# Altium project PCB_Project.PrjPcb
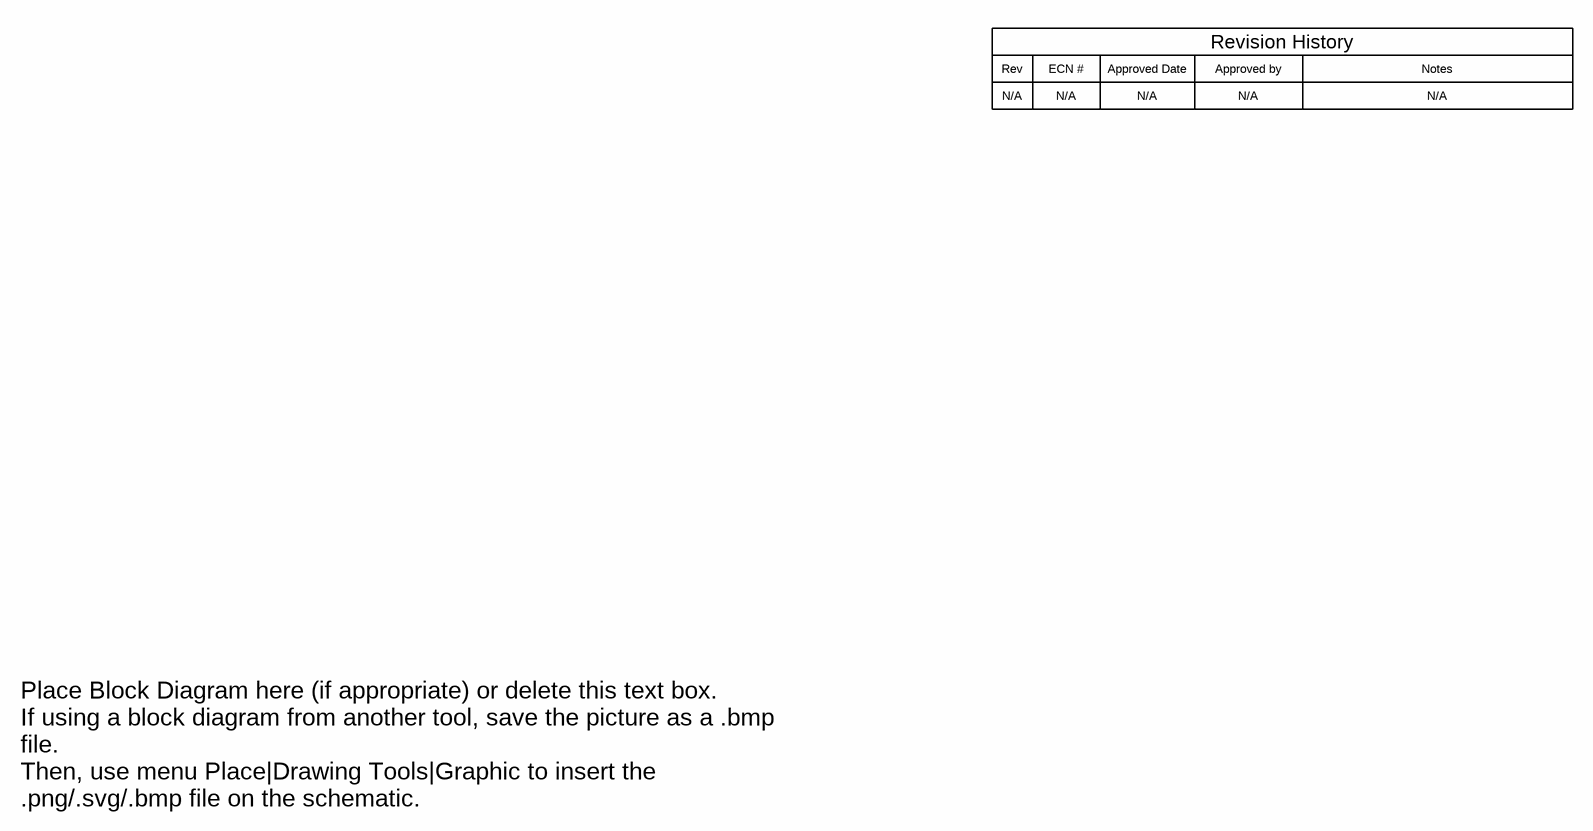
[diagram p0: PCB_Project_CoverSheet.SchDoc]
TID: 01409; TechSupport: http://www.ti.com/support; SCH_Rev: E2; PRJ_Title: Automotive Kick-to-Open Capacitve; PRJ_Number: TIDA-01409; PRJ_Engineer: C.Kinnaird; PRJ_Customer: Public Release; PCB_Rev: E1; PCB_Layout: Who did the Layout?; CopyrightYear: 2017
3 sheets, 43 parts. Net scope: global (net labels, ports and power ports of the same name join across sheets).
Board file: TIDA_01409_Layout2.PcbDoc
Sheets:
  PCB_Project_CoverSheet.SchDoc
  TIDA_01409_Schematic2.SchDoc
  PCB_Project_EVM_Hardware.SchDoc

## Sheet PCB_Project_CoverSheet.SchDoc
size 431 x 279 mm; Date: Not shown in title block; ApprovedBy: Not shown in title block; CheckedBy: Not shown in title block; Author: Not shown in title block; CompanyName: Not shown in title block; Engineer: Not shown in title block; Organization: Not shown in title block; Address1: Not shown in title block; Address2: Not shown in title block; Address3: Not shown in title block; Address4: Not shown in title block; DocumentNumber: 1; Revision: Use project parameter SCH_Rev; SheetNumber: 1; SheetTotal: 3; PageSetup: Record=PageOptions¦CenterHorizontal=True¦CenterVertical=True¦PrintScale=1.00¦XCorrection=1.00¦YCorrection=1.00¦PrintKind=0¦BorderSize=5000000¦LeftOffset=0¦BottomOffset=0¦Orientation=2¦PaperLength=1000¦PaperWidth=1000¦Scale=100¦PaperSource=15¦PrintQuality=600¦MediaType=1¦DitherType=10¦PaperKind=Letter¦PrintScaleMode=1

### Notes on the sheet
- Rev
- N/A
- ECN #
- Approved Date
- Approved by
- Revision History
- Notes
- Place Block Diagram here (if appropriate) or delete this text box.
  If using a block diagram from another tool, save the picture as a .bmp file.
  Then, use menu Place|Drawing Tools|Graphic to insert the .png/.svg/.bmp file on the schematic.

## Sheet TIDA_01409_Schematic2.SchDoc
size 431 x 279 mm; Date: Not shown in title block; ApprovedBy: Not shown in title block; CheckedBy: Not shown in title block; Author: Not shown in title block; CompanyName: Not shown in title block; Engineer: Not shown in title block; Organization: Not shown in title block; Address1: Not shown in title block; Address2: Not shown in title block; Address3: Not shown in title block; Address4: Not shown in title block; DocumentNumber: 1; Revision: Use project parameter SCH_Rev; SheetNumber: 2; SheetTotal: 3; PageSetup: Record=PageOptions¦CenterHorizontal=True¦CenterVertical=True¦PrintScale=0.98¦XCorrection=1.00¦YCorrection=1.00¦PrintKind=0¦BorderSize=5000000¦LeftOffset=0¦BottomOffset=0¦Orientation=2¦PaperLength=1000¦PaperWidth=1000¦Scale=100¦PaperSource=15¦PrintQuality=-3¦MediaType=1¦DitherType=10¦PrintScaleMode=1¦PaperKind=11×17¦PaperIndex=17
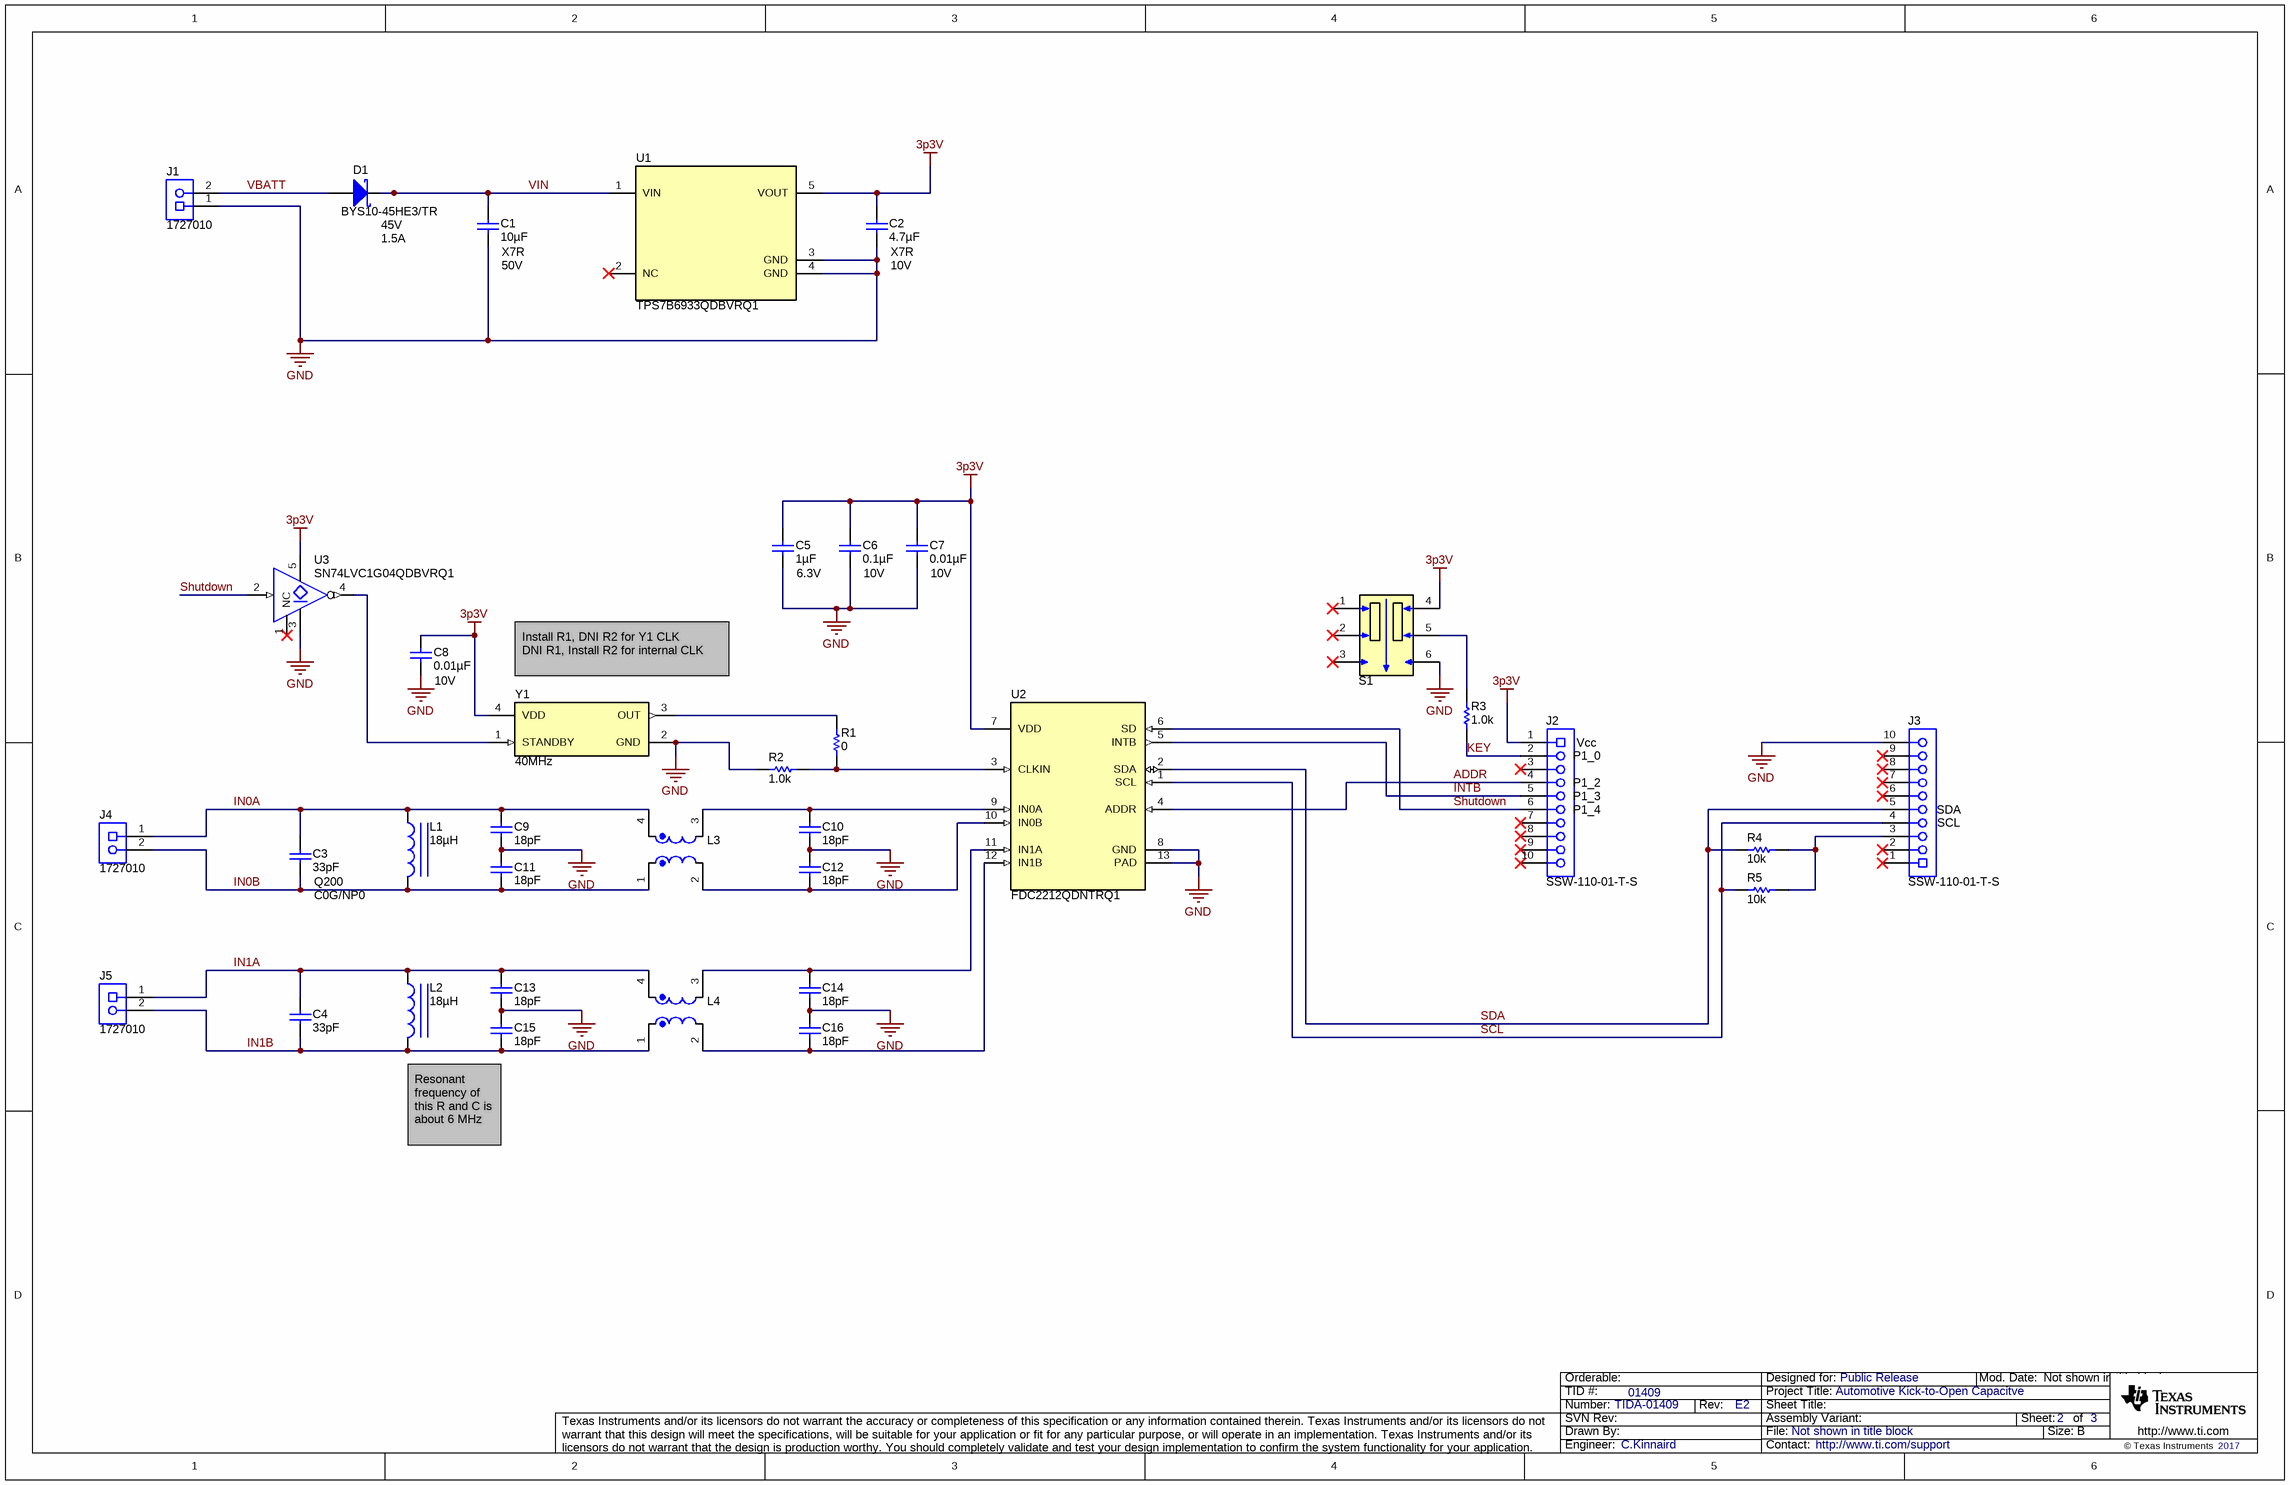
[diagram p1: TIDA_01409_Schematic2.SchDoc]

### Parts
C1  ValueDisplayed: 10µF  Value2: 50V  TempCo: X7R  [1210_280]  (hidden comment: UMK325AB7106KMHT)
C2  ValueDisplayed: 4.7µF  Value2: 10V  TempCo: X7R  [0805_HV]  (hidden comment: C2012X7R1A475M125AC)
C3  ValueDisplayed: 33pF  TempCo: C0G/NP0  AEC Category: Q200  [0603]  (hidden comment: CL10C330FB8NNNC)
C4  ValueDisplayed: 33pF  [0603]  (hidden comment: CL10C330FB8NNNC)
C5  ValueDisplayed: 1µF  Value2: 6.3V  [0603]  (hidden comment: GRM188R70J105KA01D)
C6  ValueDisplayed: 0.1µF  Value2: 10V  [0603]  (hidden comment: C0603C104K8RACTU)
C7  ValueDisplayed: 0.01µF  Value2: 10V  [0603]  (hidden comment: 0603ZC103KAT2A)
C8  ValueDisplayed: 0.01µF  Value2: 10V  [0603]  (hidden comment: 0603ZC103KAT2A)
C9  ValueDisplayed: 18pF  [0603]  (hidden comment: GRM1885C2A180JA01D)
C10  ValueDisplayed: 18pF  [0603]  (hidden comment: GRM1885C2A180JA01D)
C11  ValueDisplayed: 18pF  [0603]  (hidden comment: GRM1885C2A180JA01D)
C12  ValueDisplayed: 18pF  [0603]  (hidden comment: GRM1885C2A180JA01D)
C13  ValueDisplayed: 18pF  [0603]  (hidden comment: GRM1885C2A180JA01D)
C14  ValueDisplayed: 18pF  [0603]  (hidden comment: GRM1885C2A180JA01D)
C15  ValueDisplayed: 18pF  [0603]  (hidden comment: GRM1885C2A180JA01D)
C16  ValueDisplayed: 18pF  [0603]  (hidden comment: GRM1885C2A180JA01D)
D1  BYS10-45HE3/TR  value 45V  Value1: 1.5A  [SMA]
J1  1727010  [PhoenixConact_1727010]
J2  SSW-110-01-T-S  [Samtec_SSW-110-x1-x-S]
J3  SSW-110-01-T-S  [Samtec_SSW-110-x1-x-S]
J4  1727010  [PhoenixConact_1727010]
J5  1727010  [PhoenixConact_1727010]
L1  ValueDisplayed: 18µH  [CMH322522]  (hidden comment: CMH322522-180KL)
L2  ValueDisplayed: 18µH  [CMH322522]  (hidden comment: CMH322522-180KL)
L3  SRF3216-222Y  [SRF3216]  (value not drawn)
L4  SRF3216-222Y  [SRF3216]  (value not drawn)
R1  ValueDisplayed: 0  [0402]  (hidden comment: ERJ-2GE0R00X)
R2  ValueDisplayed: 1.0k  [0402]  (hidden comment: CRCW04021K00JNED)
R3  ValueDisplayed: 1.0k  [0402]  (hidden comment: CRCW04021K00JNED)
R4  ValueDisplayed: 10k  [0402]  (hidden comment: CRCW040210K0JNED)
R5  ValueDisplayed: 10k  [0402]  (hidden comment: CRCW040210K0JNED)
S1  JS202011CQN  [SW_JS202011CQN]  (value not drawn)
U1  TPS7B6933QDBVRQ1  [DBV0005A_N]
U2  FDC2212QDNTRQ1  [DNT0012B]
U3  SN74LVC1G04QDBVRQ1  [DBV0005A_N]
Y1  Frequency: 40MHz  [Microchip_DSC1001BI1]  (hidden comment: DSC1001BI1-040.0000)

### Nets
3p3V: C2.1 C5.1 C6.1 C7.1 C8.1 J2.1 S1.4 U1.5(VOUT) U2.7(VDD) U3.5(VCC) Y1.4(VDD)
GND: C1.2 C2.2 C5.2 C6.2 C7.2 C8.2 C9.2 C10.2 C11.1 C12.1 C13.2 C14.2 C15.1 C16.1 J1.1 J3.10 R2.1 S1.6 U1.3(GND) U1.4(GND) U2.8(GND) U2.13(PAD) U3.3(GND) Y1.2(GND)
ADDR: J2.4 U2.4(ADDR)
IN0A: C3.1 C9.1 J4.1 L1.1 L3.4
IN0B: C3.2 C11.2 J4.2 L1.2 L3.1
IN1A: C4.1 C13.1 J5.1 L2.1 L4.4
IN1B: C4.2 C15.2 J5.2 L2.2 L4.1
INTB: J2.5 U2.5(INTB)
KEY: J2.2 R3.1
SCL: J3.4 R5.1 U2.1(SCL)
SDA: J3.5 R4.1 U2.2(SDA)
Shutdown: J2.6 U2.6(SD) U3.2(A)
VBATT: D1.2(A) J1.2
VIN: C1.1 D1.1(K) U1.1(VIN)
NetC10_1: C10.1 L3.3 U2.9(IN0A)
NetC12_2: C12.2 L3.2 U2.10(IN0B)
NetC14_1: C14.1 L4.3 U2.11(IN1A)
NetC16_2: C16.2 L4.2 U2.12(IN1B)
NetJ3_3: J3.3 R4.2 R5.2
NetR1_1: R1.1 R2.2 U2.3(CLKIN)
NetR1_2: R1.2 Y1.3(OUT)
NetR3_2: R3.2 S1.5(C)
NetU3_4: U3.4(Y) Y1.1(STANDBY)

Not connected (* = marked no-connect by the designer): J2 3* 7* 8* 9* 10*; J3 1* 2* 6* 7* 8* 9*; S1 1* 2(C)* 3*; U1 2(NC)*; U3 1(NC)*

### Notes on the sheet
- (near Y1) Install R1, DNI R2 for Y1 CLK
  DNI R1, Install R2 for internal CLK
- (near J2) Vcc
- (near J2) P1_0
- (near J2) P1_2
- (near J2) P1_3
- (near J2) P1_4
- (near J3) SDA
- (near J3) SCL
- Resonant frequency of this R and C is about 6 MHz

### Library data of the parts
C1 = UMK325AB7106KMHT: CAP, CERM, 10 µF, 50 V, +/- 10%, X7R, AEC-Q200 Grade 1, 1210; Manufacturer: Taiyo Yuden; Polarized: N; CompType: Capacitor; Value: 10uF; U/M: EA; Cap_F: 0.00001; Tolerance_%: 10; Value1: Unknown; VDC_V: 50; TaMin_C: -55; TaMax_C: 125; Cap_Case: 1210; SizeArea_mm2: 8; SizeAreaWB_mm2: 14.7; SizeX_mm: 3.2; SizeY_mm: 2.5; SizeZ_mm: 2.8; AEC Category: Q200; AEC Qualified: Y; AEC Grade: 1
C2 = C2012X7R1A475M125AC: CAP, CERM, 4.7 µF, 10 V, +/- 20%, X7R, 0805; Manufacturer: TDK; Polarized: N; CompType: Capacitor; Value: 4.7uF; U/M: EA; Cap_F: 0.0000047; Tolerance_%: 20; Value1: Unknown; VDC_V: 10; TaMin_C: -55; TaMax_C: 125; Cap_Case: 0805; SizeArea_mm2: 2.5; SizeAreaWB_mm2: 6.75; SizeX_mm: 2; SizeY_mm: 1.25; SizeZ_mm: 1.45; AEC Category: Q200
C3 = CL10C330FB8NNNC: CAP, CERM, 33 pF, 50 V, +/- 5%, C0G/NP0, 0603; Manufacturer: Samsung Electro-Mechanics; Polarized: N; CompType: Capacitor; Value: 33pF; U/M: EA; Cap_F: 0.000000000033; Tolerance_%: 5; Value1: Unknown; VDC_V: 50; Value2: 50V; TaMin_C: -55; TaMax_C: 125; SizeArea_mm2: 1.28; SizeAreaWB_mm2: 4.68; SizeX_mm: 1.6; SizeY_mm: 0.8; SizeZ_mm: 1
C4 = CL10C330FB8NNNC: CAP, CERM, 33 pF, 50 V, +/- 5%, C0G/NP0, 0603; Manufacturer: Samsung Electro-Mechanics; Polarized: N; CompType: Capacitor; Value: 33pF; U/M: EA; Cap_F: 0.000000000033; Tolerance_%: 5; Value1: Unknown; VDC_V: 50; Value2: 50V; TaMin_C: -55; TaMax_C: 125; SizeArea_mm2: 1.28; SizeAreaWB_mm2: 4.68; SizeX_mm: 1.6; SizeY_mm: 0.8; SizeZ_mm: 1; AEC Category: Q200
C5 = GRM188R70J105KA01D: CAP, CERM, 1 µF, 6.3 V, +/- 10%, X7R, 0603; Manufacturer: MuRata; Polarized: N; CompType: Capacitor; Value: 1uF; U/M: EA; Cap_F: 0.000001; Tolerance_%: 10; Value1: Unknown; VDC_V: 6.3; TaMin_C: -55; TaMax_C: 125; SizeArea_mm2: 1.28; SizeAreaWB_mm2: 4.68; SizeX_mm: 1.6; SizeY_mm: 0.8; SizeZ_mm: 1; AEC Category: Q200
C6 = C0603C104K8RACTU: CAP, CERM, 0.1 µF, 10 V, +/- 10%, X7R, 0603; Manufacturer: Kemet; Polarized: N; CompType: Capacitor; Value: 0.1uF; U/M: EA; Cap_F: 0.0000001; Tolerance_%: 10; Value1: Unknown; TaMin_C: -55; TaMax_C: 125; SizeArea_mm2: 1.28; SizeAreaWB_mm2: 4.68; SizeX_mm: 1.6; SizeY_mm: 0.8; SizeZ_mm: 1; AEC Category: Q200
C7 C8 = 0603ZC103KAT2A: CAP, CERM, 0.01 µF, 10 V, +/- 10%, X7R, 0603; Manufacturer: AVX; Polarized: N; CompType: Capacitor; Value: 0.01uF; U/M: EA; Cap_F: 0.00000001; Tolerance_%: 10; Value1: Unknown; TaMin_C: -55; TaMax_C: 125; SizeArea_mm2: 1.28; SizeAreaWB_mm2: 4.68; SizeX_mm: 1.6; SizeY_mm: 0.8; SizeZ_mm: 1; AEC Category: Q200
C9-C16 = GRM1885C2A180JA01D: CAP, CERM, 18 pF, 100 V, +/- 5%, C0G/NP0, 0603; Manufacturer: MuRata; Polarized: N; CompType: Capacitor; Value: 18pF; U/M: EA; Cap_F: 0.000000000018; Tolerance_%: 5; Value1: Unknown; VDC_V: 100; Value2: 100V; TaMin_C: -55; TaMax_C: 125; SizeArea_mm2: 1.28; SizeAreaWB_mm2: 4.68; SizeX_mm: 1.6; SizeY_mm: 0.8; SizeZ_mm: 1; AEC Category: Q200
D1 = BYS10-45HE3/TR: Diode, Schottky, 45 V, 1.5 A, AEC-Q101, SMA; Manufacturer: Vishay-Semiconductor; U/M: EA; Vf_V: 0.5; Value2: 0.5V; Io_A: 1.5; Vr_V: 45; TJmax_C: 150; SizeAreaWB_mm2: 37.3428; SizeArea_mm2: 16.3228; SizeX_mm: 5.59; SizeY_mm: 2.92; SizeZ_mm: 2.87; AEC Category: Q101; AEC Qualified: Y
J1 J4 J5 = 1727010: Conn Term Block, 2POS, 3.81mm, TH; Manufacturer: Phoenix Contact; SymbolCreator: a0412235; CompType: Terminal Block
J2 J3 = SSW-110-01-T-S: Receptacle, 2.54mm, 10x1, Tin, TH; Manufacturer: Samtec; SymbolCreator: a0411947; Pitch_mm: 2.54; Gender: Female; Row_Count: 1; Cert_CSA: Y
L1 L2 = CMH322522-180KL: Inductor, Shielded, Ferrite, 18 µH, 0.12 A, 3.3 ohm, SMD; Manufacturer: Bourns; Value: 18uH; Ind_H: 18.0E-6; Imax_A: 0.12; Irms: 0.12A @ 20C rise; DCR_ohm: 3.3; Value1: 3.3 ohm; Value2: 0.12A; SizeAreaWB_mm2: 14.7; SizeArea_mm2: 8; SizeX_mm: 3.2; SizeY_mm: 2.5; SizeZ_mm: 2.4; AEC Category: Q200; AEC Qualified: N
L3 L4 = SRF3216-222Y: Inductor, Wirewound, Ferrite, 0.2 A, 1.2 ohm, SMD; Manufacturer: Bourns; SymbolCreator: a0411947; Imax_A: 0.2; DCR_ohm: 1.2; Value1: 1.2 ohm; Value2: 0.2A; SizeAreaWB_mm2: 10.92; SizeArea_mm2: 5.12; SizeX_mm: 3.2; SizeY_mm: 1.6; SizeZ_mm: 2.2; AEC Category: Q200
R1 = ERJ-2GE0R00X: RES, 0, 5%, 0.063 W, 0402; Manufacturer: Panasonic; CompType: Resistor; Value: 0; Value_Code: 0000; Tolerance_%: 5; Power_W: 0.063; Value2: 0.063W; VDC_V: 50; TempCo: 600 ppm/C; SizeArea_mm2: 0.5; SizeX_mm: 1; SizeZ_mm: 0.6; EIA_Code: E24; U/M: EA; AEC Category: Q200
R2 R3 = CRCW04021K00JNED: RES, 1.0 k, 5%, 0.063 W, 0402; Manufacturer: Vishay-Dale; CompType: Resistor; Value: 1.0k; Res_ohm: 1000; Value_Code: 1k00; Tolerance_%: 5; Power_W: 0.063; Value2: 0.063W; VDC_V: 50; TempCo: 200 ppm/C; SizeArea_mm2: 0.5; SizeX_mm: 1; SizeZ_mm: 0.6; EIA_Code: E24; U/M: EA; AEC Category: Q200
R4 R5 = CRCW040210K0JNED: RES, 10 k, 5%, 0.063 W, 0402; Manufacturer: Vishay-Dale; CompType: Resistor; Value: 10k; Res_ohm: 10000; Value_Code: 10k0; Tolerance_%: 5; Power_W: 0.063; Value2: 0.063W; VDC_V: 50; TempCo: 200 ppm/C; SizeArea_mm2: 0.5; SizeX_mm: 1; SizeZ_mm: 0.6; EIA_Code: E24; U/M: EA; AEC Category: Q200
S1 = JS202011CQN: Slide Switch, DPDT, 0.3A 6VDC, TH; Manufacturer: C&K Components; SymbolCreator: x0208325; VDC_V: 6; SwitchFunction: On-On; PositionCount: 1; CurrentRating_mA: 300
U1 = TPS7B6933QDBVRQ1: High Voltage Ultra Low Iq - Low Drop Out Regulator, DBV0005A (SOT-5); Manufacturer: Texas Instruments; SymbolCreator: Altium; SizeArea_mm2: 8.12; SizeAreaWB_mm2: 14.82; SizeX_mm: 2.8; SizeY_mm: 2.9; SizeZ_mm: 1.45; CompType: IC; U/M: EA
U2 = FDC2212QDNTRQ1: Multi-Channel 12-Bit or 28-Bit Capacitance-to-Digital Converter (FDC) for Capacitive Sensing, DNT0012B (WSON-12); Alternate PartNumber: FDC2212QDNTTQ1; Manufacturer: Texas Instruments; SymbolCreator: a0411947; SizeArea_mm2: 16; SizeAreaWB_mm2: 25; SizeX_mm: 4; SizeZ_mm: 0.8; CompType: IC; U/M: EA
U3 = SN74LVC1G04QDBVRQ1: Automotive Catalog Single Inverter, DBV0005A (SOT-5); Manufacturer: Texas Instruments; SymbolCreator: a0411947; SizeArea_mm2: 8.12; SizeAreaWB_mm2: 14.82; SizeX_mm: 2.8; SizeY_mm: 2.9; SizeZ_mm: 1.45; CompType: IC; U/M: EA
Y1 = DSC1001BI1-040.0000: OSC, 4MHz, CMOS, 1.8 to 3.3V, SMD; Manufacturer: Microchip; SymbolCreator: Altium; CompType: Oscillator; SizeAreaWB_mm2: 36.4; SizeArea_mm2: 16; SizeX_mm: 3.2; SizeY_mm: 5; SizeZ_mm: 0.9; U/M: EA; TaMin_C: -40; TaMax_C: 85; Frequency Stability: ±50ppm

## Sheet PCB_Project_EVM_Hardware.SchDoc
size 431 x 279 mm; Date: Not shown in title block; ApprovedBy: Not shown in title block; CheckedBy: Not shown in title block; Author: Not shown in title block; CompanyName: Not shown in title block; Engineer: Not shown in title block; Organization: Not shown in title block; Address1: Not shown in title block; Address2: Not shown in title block; Address3: Not shown in title block; Address4: Not shown in title block; DocumentNumber: 1; Revision: Use project parameter SCH_Rev; SheetNumber: 3; SheetTotal: 3; PageSetup: Record=PageOptions¦CenterHorizontal=True¦CenterVertical=True¦PrintScale=1.00¦XCorrection=1.00¦YCorrection=1.00¦PrintKind=0¦BorderSize=5000000¦LeftOffset=0¦BottomOffset=0¦Orientation=2¦PaperLength=1000¦PaperWidth=1000¦Scale=100¦PaperSource=15¦PrintQuality=600¦MediaType=1¦DitherType=10¦PaperKind=Letter¦PrintScaleMode=1
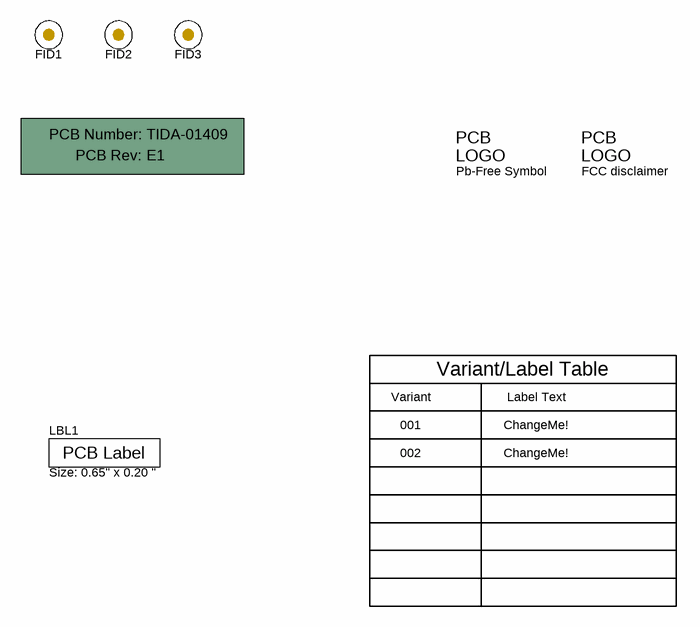
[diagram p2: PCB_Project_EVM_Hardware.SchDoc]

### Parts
!PCB  Printed Circuit Board  (value not drawn)  (mechanical)
FID1  Fiducial  [Fiducial10-20]  (value not drawn)
FID2  Fiducial  [Fiducial10-20]  (value not drawn)
FID3  Fiducial  [Fiducial10-20]  (value not drawn)
LBL1  Size: 0.65" x 0.20 "  [Label_650x200]
Logo2  Pb-Free Symbol  [Pb-Free_Overlay_Small]  (no BOM)
Logo3  FCC disclaimer  [FCC_disclaimer]  (no BOM)

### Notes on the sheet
- Variant
- Variant/Label Table
- Label Text
- 001
- 002
- ChangeMe!

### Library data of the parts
!PCB = PCB: Manufacturer: Any; PartNumber: TIDA-01409; SymbolCreator: a0412235
FID1-FID3 = Fiducial: Fiducial mark.  There is nothing to buy or mount.; SymbolCreator: codlsc
LBL1 = THT-14-423-10: Thermal Transfer Printable Labels, 0.650" W x 0.200" H - 10,000 per roll; Manufacturer: Brady; SymbolCreator: a0412235; CompType: Label
Logo2 = Pb-Free: SymbolCreator: a0412235
Logo3 = FCC_disclaimer: SymbolCreator: codlsc

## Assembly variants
001: not fitted C9 C10 C11 C12 C13 C14 C15 C16 FID1 FID2 FID3 L3 L4 R2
